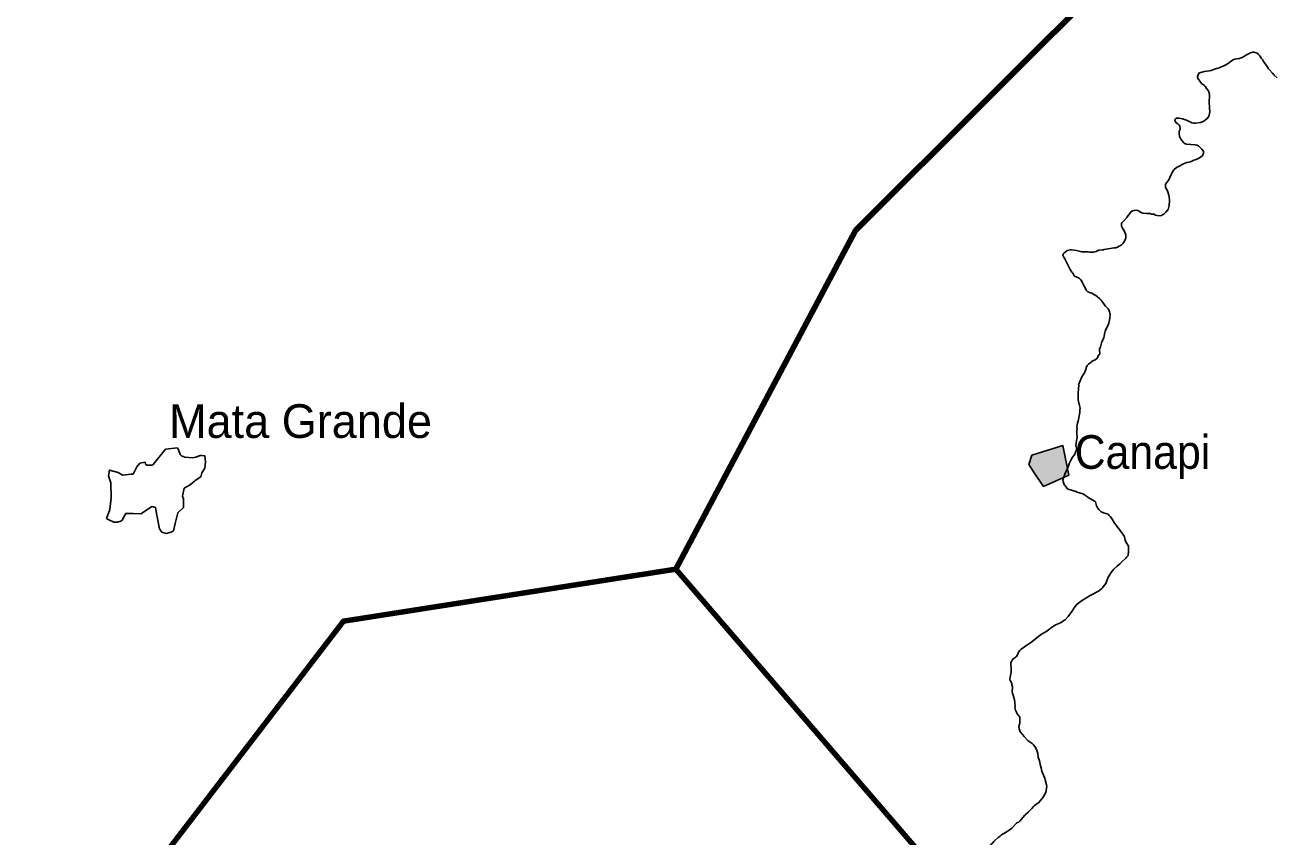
# Model space of a CAD drawing. Extents: x 553962 to 842807, y 8883888 to 9032388.
# Drawn here: x 637499 to 656083, y 8986538 to 8998597 of the extents above; entities that cross this region are included whole.
import ezdxf

# ---------------------------------------------------------------- set-up
doc = ezdxf.new("R2010")
doc.units = 0
doc.header["$LTSCALE"] = 200
for name, color, linetype, lineweight in [('21', 7, 'Continuous', 25), ('24', 7, 'Continuous', 25), ('9', 7, 'Continuous', 90)]:
    doc.layers.add(name, color=color, linetype=linetype, lineweight=lineweight)
doc.layers.add('41', color=7, linetype='Continuous')

msp = doc.modelspace()

# ---------------------------------------------------------------- hatches: boundary and pattern name
at = {"layer": '21'}
msp.add_hatch(color=256, dxfattribs=at).paths.add_polyline_path([(652442.2, 8992209.7), (652905.2, 8992350.1), (652993.5, 8991912.7), (652618.8, 8991744.3), (652496.7, 8991914.1), (652399.6, 8992070.3)])

# ---------------------------------------------------------------- linework, layer by layer
for points in [[(639985.7, 8992170.7), (640033.2, 8992177.5), (640101, 8992204.6), (640121.3, 8992204.6), (640168.8, 8992197.9), (640175.6, 8992109.7), (640168.8, 8992014.7), (640121.3, 8991946.8), (640107.8, 8991885.7), (640026.4, 8991831.5), (639951.8, 8991770.4), (639863.6, 8991716.1), (639836.5, 8991600.8), (639850, 8991560.1), (639850, 8991431.1), (639768.6, 8991349.7), (639727.9, 8991193.7), (639700.8, 8991085.1), (639666.9, 8991064.8), (639646.5, 8991058), (639592.3, 8991044.4), (639531.2, 8991064.8), (639497.3, 8991112.2), (639456.6, 8991315.8), (639436.3, 8991431.1), (639382, 8991444.7), (639300.6, 8991390.4), (639219.2, 8991336.2), (639103.9, 8991342.9), (638995.4, 8991342.9), (638954.7, 8991275.1), (638947.9, 8991248), (638920.8, 8991227.6), (638873.3, 8991214), (638819, 8991214), (638730.8, 8991254.7), (638710.5, 8991268.3), (638758, 8991404), (638778.3, 8991573.6), (638771.6, 8991797.5), (638737.6, 8991899.3), (638751.2, 8991987.5), (638880.1, 8991953.6), (638947.9, 8991912.9), (639076.8, 8991926.5), (639103.9, 8991926.5), (639158.2, 8992035), (639205.7, 8992089.3), (639280.3, 8992102.9), (639287, 8992075.7), (639307.4, 8992062.2), (639327.7, 8992062.2), (639348.1, 8992062.2), (639382, 8992062.2), (639402.3, 8992068.9), (639585.5, 8992299.6), (639761.8, 8992320), (639782.2, 8992272.5), (639802.5, 8992218.2), (639822.9, 8992197.9), (639870.4, 8992177.5)], [(652442.2, 8992209.7), (652905.2, 8992350.1), (652993.5, 8991912.7), (652618.8, 8991744.3), (652496.7, 8991914.1), (652399.6, 8992070.3)]]:
    msp.add_lwpolyline(points, close=True, dxfattribs=at)
at = {"layer": '24'}
for points in [[(656084.2, 8997812.2), (656040, 8997850.5), (656017.7, 8997880.1), (655973.3, 8997930.8), (655954.3, 8997950.2), (655940.7, 8997978.6), (655923.1, 8998001.5), (655883.5, 8998057.7), (655867.9, 8998085.6), (655850.3, 8998107.5), (655828.3, 8998139.1), (655810.7, 8998161.9), (655799.2, 8998173.1), (655776, 8998185.7), (655740.7, 8998194.2), (655726.6, 8998194.9), (655688, 8998185.3), (655639.5, 8998162), (655564, 8998115.9), (655536.1, 8998103), (655526.2, 8998099.9), (655484.5, 8998096.5), (655459.7, 8998090.2), (655434.8, 8998080.9), (655409, 8998064), (655359.2, 8998025.6), (655313.6, 8997999.2), (655285.5, 8997987.2), (655210, 8997959), (655183.6, 8997951.1), (655157.8, 8997940.5)], [(655157.8, 8997940.5), (655107.3, 8997923.6), (655079.9, 8997916.8), (655003.7, 8997905.1), (654951.8, 8997893.1), (654921.9, 8997881.5), (654911.5, 8997859.3), (654904.5, 8997835.3), (654903.3, 8997818.2), (654921.4, 8997783.2), (654936.6, 8997761.1), (654963.8, 8997729.2), (655008.4, 8997696.8), (655009.5, 8997691.4), (655015.2, 8997687.5), (655037.5, 8997653.3), (655064.5, 8997618.3), (655082.6, 8997567.8), (655083.8, 8997539.5), (655075.5, 8997462.4), (655082.9, 8997361.5), (655083.9, 8997309.2), (655081.8, 8997284.4), (655077.8, 8997260.5), (655067.6, 8997232.5), (655062.5, 8997223.8), (655056.8, 8997221.5), (655046.8, 8997210), (655019.8, 8997187.1), (654997.2, 8997170), (654975.4, 8997159), (654947.2, 8997150.5), (654874, 8997139.2), (654845.3, 8997141.1), (654819.7, 8997146.5), (654794, 8997157.1), (654769.6, 8997171.2)], [(654769.6, 8997171.2), (654738.3, 8997183.8), (654678.4, 8997205.1), (654627.8, 8997215.7), (654601.5, 8997215.8), (654591.6, 8997213.9), (654575.8, 8997201.7), (654567.6, 8997179.6), (654577.8, 8997158.2), (654585.5, 8997146.5), (654609.2, 8997130.1), (654609.2, 8997130.1), (654631.1, 8997112.1), (654638.8, 8997103.7), (654643.1, 8997086.6), (654646.1, 8997060.5), (654644.8, 8997050.5), (654633.6, 8997030.5), (654630.6, 8997005), (654630.3, 8996976.2), (654634.6, 8996950.6), (654637.9, 8996939.8), (654647.7, 8996924), (654661.2, 8996897.6), (654676.9, 8996874.9), (654700.6, 8996846.2), (654711, 8996839.6), (654738.5, 8996827.7), (654866.3, 8996819.7), (654894.5, 8996812.3), (654917.5, 8996801), (654942.4, 8996779.5), (654967.7, 8996755.2), (654988.5, 8996728.4), (654992.8, 8996711.5), (654991.8, 8996695.7), (654982.3, 8996670.2), (654975.7, 8996656.4), (654924.5, 8996618.8), (654884, 8996599.8), (654848.8, 8996588.4), (654798.2, 8996566.4), (654746.9, 8996553.3), (654696.3, 8996535.5), (654621.2, 8996498.1), (654593.2, 8996479), (654553.4, 8996444.2), (654534.4, 8996418.2), (654494.6, 8996332.7), (654480.8, 8996307), (654464.3, 8996280.6), (654430.7, 8996233.3), (654427.9, 8996227.3), (654425.9, 8996202.2), (654427.1, 8996188.5), (654434.5, 8996173.5), (654452.9, 8996147), (654465.3, 8996122.1), (654480.1, 8996071.6), (654484.6, 8996045.1), (654486.7, 8995992.8), (654483.6, 8995917.5), (654474.7, 8995876.7), (654467.9, 8995855), (654434.3, 8995816.1)], [(654434.3, 8995816.1), (654405, 8995790.5), (654383.8, 8995777), (654370.8, 8995770.5), (654331.6, 8995764.8), (654305.1, 8995767.1), (654280.3, 8995774.4), (654256.6, 8995785.8), (654222.5, 8995790.4), (654197.6, 8995796.5), (654144.6, 8995796.9), (654094.1, 8995804.4), (654067.8, 8995813.2), (654058.9, 8995818.6), (654053.8, 8995824.2), (654017.8, 8995841.2), (653993.1, 8995845.7), (653966.6, 8995843.9), (653958.3, 8995840.5), (653940.7, 8995836.5), (653915.1, 8995821.7), (653896.5, 8995797.2), (653873.6, 8995770), (653853, 8995739.7), (653809.9, 8995690.5), (653777.6, 8995659.6), (653777, 8995649.1), (653773.2, 8995638.5), (653777.4, 8995608.5), (653788.4, 8995582), (653803, 8995557.1), (653819.9, 8995531.3), (653830.7, 8995505.7), (653837.4, 8995477), (653839.2, 8995454.3), (653837.3, 8995430.5), (653832.8, 8995422.3)], [(653832.8, 8995422.3), (653826.6, 8995401.3), (653812.5, 8995377.3), (653793.7, 8995351), (653775.3, 8995332.6), (653765.9, 8995326.3), (653761.2, 8995324.9), (653757.5, 8995320), (653742.2, 8995313.6), (653716.5, 8995297.9), (653691.6, 8995289.7), (653664.8, 8995287.2), (653664.8, 8995287.2), (653516.9, 8995264.1), (653510.9, 8995259.8), (653490.9, 8995260.2), (653437.7, 8995252), (653396.8, 8995235.5), (653378.3, 8995229.4), (653359, 8995225.3), (653302.9, 8995225.3), (653282, 8995227.4), (653188.1, 8995230.6), (653109.4, 8995250.9), (653073.5, 8995253.9), (653034, 8995259.3), (653013.9, 8995258.4), (652993, 8995253.1), (652967.8, 8995250.4), (652934.9, 8995220), (652921.1, 8995209.2), (652910.5, 8995196.7), (652906.3, 8995176.7), (652907.7, 8995171), (652922.2, 8995141.9), (652932.8, 8995125.7), (652973.4, 8995043.3), (652981.4, 8995023.3), (653011, 8994966.3), (653037.8, 8994927.2), (653051.9, 8994911.9), (653062.4, 8994891.4), (653073.2, 8994874.3), (653086.7, 8994861.3), (653129, 8994846), (653146.4, 8994835.2), (653168.3, 8994817.2), (653170.7, 8994809.8), (653175.5, 8994807.6), (653191.3, 8994784), (653196.5, 8994768.7), (653211.1, 8994737.3), (653243.9, 8994674.7), (653252.4, 8994660.6), (653276.2, 8994633.6), (653299.1, 8994625.2), (653319.2, 8994620.5), (653334.8, 8994613.7), (653376.3, 8994588.9), (653394.7, 8994579.6), (653411.9, 8994563.4), (653455, 8994528.4), (653472.3, 8994508.8), (653537, 8994423.4), (653575.4, 8994381.7)], [(653575.4, 8994381.7), (653586.1, 8994365.1), (653599.4, 8994339.1), (653603.8, 8994319.8), (653604.9, 8994300.6), (653603.7, 8994242.8), (653588.1, 8994167.4), (653576.4, 8994144.9), (653533.3, 8994050.1), (653528, 8994030.9), (653518.3, 8993973.9), (653513.3, 8993955.5), (653488.2, 8993896.1), (653478.4, 8993876), (653466.1, 8993839), (653461.5, 8993819), (653450.8, 8993784.2), (653449.9, 8993778), (653451.5, 8993712.6), (653424.2, 8993677.3), (653424.4, 8993666.2), (653409.3, 8993643), (653384.1, 8993623.8), (653360.3, 8993615.7), (653334.2, 8993599.6), (653308, 8993581.4), (653282.8, 8993560), (653264.2, 8993540.2), (653251.9, 8993507.8), (653244.3, 8993482.9), (653237.7, 8993455.1), (653227.3, 8993430.2), (653188.7, 8993371.5), (653138.5, 8993253.8), (653138.8, 8993251.9), (653143, 8993247.7), (653131.9, 8993133.2)], [(653131.9, 8993133.2), (653129.8, 8993095.5), (653129.8, 8993054.8), (653132.2, 8993032.7), (653154.1, 8992948.6), (653155.5, 8992926.4), (653159.5, 8992905), (653155.4, 8992882), (653154.2, 8992844.1), (653130, 8992712), (653121.3, 8992682.4), (653116.5, 8992659.7), (653112.8, 8992631.9), (653112.8, 8992631.9), (653114.6, 8992605.4), (653111.6, 8992579.7), (653110.6, 8992554.8), (653113.8, 8992526.5), (653114.7, 8992476.9), (653112.5, 8992450.4), (653097.3, 8992353.7), (653111.6, 8992293.5), (653103.8, 8992279.2), (653085.8, 8992232.9), (653072.4, 8992208), (653050.1, 8992176.5), (653018, 8992124.4), (653004.3, 8992095.5), (652995.7, 8992065.1), (652985.9, 8992037.3), (652960.2, 8991981.7), (652933.3, 8991927.6), (652922.2, 8991899), (652906.4, 8991844.2), (652907.4, 8991815.5), (652917.9, 8991785.6), (652928.3, 8991762.9), (652936.6, 8991754.8), (652972.6, 8991709.8), (652998, 8991697.6), (653032.3, 8991688.1), (653060.2, 8991678.6), (653088, 8991673), (653117.6, 8991659.7), (653200.1, 8991632), (653227.9, 8991617), (653254.2, 8991600.8), (653281.5, 8991577.5), (653374.7, 8991524.4), (653387.3, 8991514.2), (653395.1, 8991496.5), (653404.1, 8991457.2), (653422.9, 8991419.4), (653438.6, 8991399.9), (653475.1, 8991367.3), (653508.4, 8991350.8), (653576.3, 8991330.8), (653594.5, 8991314.9), (653612.9, 8991293.9), (653637.5, 8991258.2), (653673.5, 8991199.1), (653693.7, 8991170.7), (653717.8, 8991140.5), (653744.1, 8991102.8), (653767.6, 8991074.9)], [(653767.6, 8991074.9), (653795.9, 8991037.1), (653814.2, 8991005.1), (653819.1, 8990993.8), (653828.8, 8990946.5), (653839.4, 8990921.2), (653878.5, 8990856.4), (653879.2, 8990781.4), (653873.4, 8990717.3), (653871, 8990712.8), (653853.9, 8990697.7), (653837.6, 8990680.5), (653785.8, 8990630.7), (653750.5, 8990593.4), (653711.8, 8990560), (653662.3, 8990513.6), (653630.7, 8990479.8), (653595.3, 8990428), (653578.7, 8990397.2), (653540.2, 8990301.5), (653523.5, 8990277.3), (653486.5, 8990235.3), (653446.5, 8990200.6), (653425.8, 8990184.6), (653406.2, 8990172.3), (653360.6, 8990147.5), (653312, 8990125.2), (653268.2, 8990099.5), (653207.5, 8990058.7), (653167.3, 8990033.5), (653113.8, 8989990.5), (653082.7, 8989954.3), (653036.6, 8989884.2), (652982.6, 8989813.8), (652936.7, 8989764.3), (652918.9, 8989751.1), (652899.7, 8989740.2)], [(652899.7, 8989740.2), (652877.8, 8989724.6), (652836.2, 8989703.3), (652811.9, 8989693.2), (652790, 8989682.3), (652749.2, 8989657.7), (652728.4, 8989641.9), (652709.2, 8989630), (652689.8, 8989614.1), (652651, 8989586.8), (652630, 8989575.5), (652587.2, 8989548.7), (652545.8, 8989519.3), (652446.2, 8989438), (652446.2, 8989438), (652410.2, 8989412.3), (652385.6, 8989397.2), (652285, 8989325.6), (652267.2, 8989307.9), (652248.4, 8989284.7), (652242.1, 8989265.4), (652232.1, 8989243.5), (652215.8, 8989220.3), (652206.6, 8989210.3), (652200.3, 8989208.7), (652190.4, 8989198.3), (652168.8, 8989181.8), (652154.9, 8989167.7), (652143.1, 8989149.5), (652131.2, 8989121), (652131.3, 8989114.2), (652134.5, 8989097.5), (652135.6, 8989052.2), (652139.7, 8989027.8), (652138.8, 8988983.3), (652120.9, 8988912.6), (652118.5, 8988880.4), (652123.9, 8988863.8), (652137.1, 8988840.6), (652156.5, 8988767.1), (652156.8, 8988741.8), (652151.8, 8988718.2), (652153.8, 8988694.7), (652158.1, 8988671.2), (652167.3, 8988644.8), (652184.8, 8988576.2), (652192.3, 8988528.1), (652195.3, 8988482.8), (652193.6, 8988458.5), (652201.4, 8988423.1), (652217.2, 8988390.3), (652226.7, 8988365.1), (652264.8, 8988314.8), (652267, 8988246.6), (652264.4, 8988229.4), (652253.4, 8988181), (652254.7, 8988143.9), (652270.8, 8988101.7), (652281, 8988087), (652329, 8988030.6), (652374.2, 8987979.9), (652391.1, 8987963.9), (652449.4, 8987924.6), (652469.8, 8987905.5), (652490.7, 8987881.2)], [(652490.7, 8987881.2), (652510.2, 8987846.4), (652519.9, 8987822.7), (652531.8, 8987775.1), (652540.2, 8987720.8), (652559.2, 8987669.4), (652563, 8987642), (652575.2, 8987593.2), (652584.9, 8987566.7), (652594.7, 8987515.3), (652603.6, 8987488.8), (652636.3, 8987409.7), (652643.8, 8987386.9), (652663.7, 8987311.6), (652665.1, 8987293.7), (652652.1, 8987197.7), (652601.8, 8987114.5), (652592.4, 8987105.1), (652542, 8987045.6), (652523, 8987034.7), (652498.3, 8987014.5), (652473.8, 8986997.1), (652445.6, 8986961.2), (652394.6, 8986912.1), (652389.2, 8986902.9), (652383.7, 8986900.8), (652349.6, 8986870.9), (652341.4, 8986859.7), (652310.3, 8986826.2), (652270.8, 8986778.6), (652249.9, 8986759.8), (652233.3, 8986751.7), (652218.9, 8986741.6), (652147.1, 8986669.5), (652105.7, 8986637.3), (652080.2, 8986619.2), (652052.1, 8986604.5)], [(652052.1, 8986604.5), (651993.9, 8986569.6), (651971.7, 8986550), (651946.1, 8986530.7), (651898, 8986488.9), (651877.6, 8986468.5), (651854.5, 8986442.5), (651837.6, 8986428.4), (651828.3, 8986417.3), (651817.8, 8986407.5), (651807.8, 8986394.7), (651766.1, 8986356.4), (651718, 8986321.2), (651688.2, 8986303.1), (651658.1, 8986282.5), (651658.1, 8986282.5), (651626.9, 8986265.4), (651599.8, 8986244.4), (651559.2, 8986206.1), (651520.7, 8986168.7)]]:
    msp.add_lwpolyline(points, dxfattribs=at)
at = {"layer": '9'}
msp.add_line((647160.3, 8990514), (659714.4, 8975927.2), dxfattribs=at)
msp.add_lwpolyline([(635350.7, 8977923.9), (636116.8, 8981777.4), (642228, 8989744.8), (647160.3, 8990514), (649828, 8995545.6), (655722.5, 9001435.5), (661506.7, 9009120.3)], dxfattribs=at)

# ---------------------------------------------------------------- texts
at = {"layer": '41'}
msp.add_text('Mata Grande', height=500, dxfattribs=at).set_placement((639637.3, 8992464.7))
at = {"layer": '41', "width": 0.95}
msp.add_text('Canapi', height=500, dxfattribs=at).set_placement((653080.1, 8992005.4))

doc.saveas('drawing.dxf')
